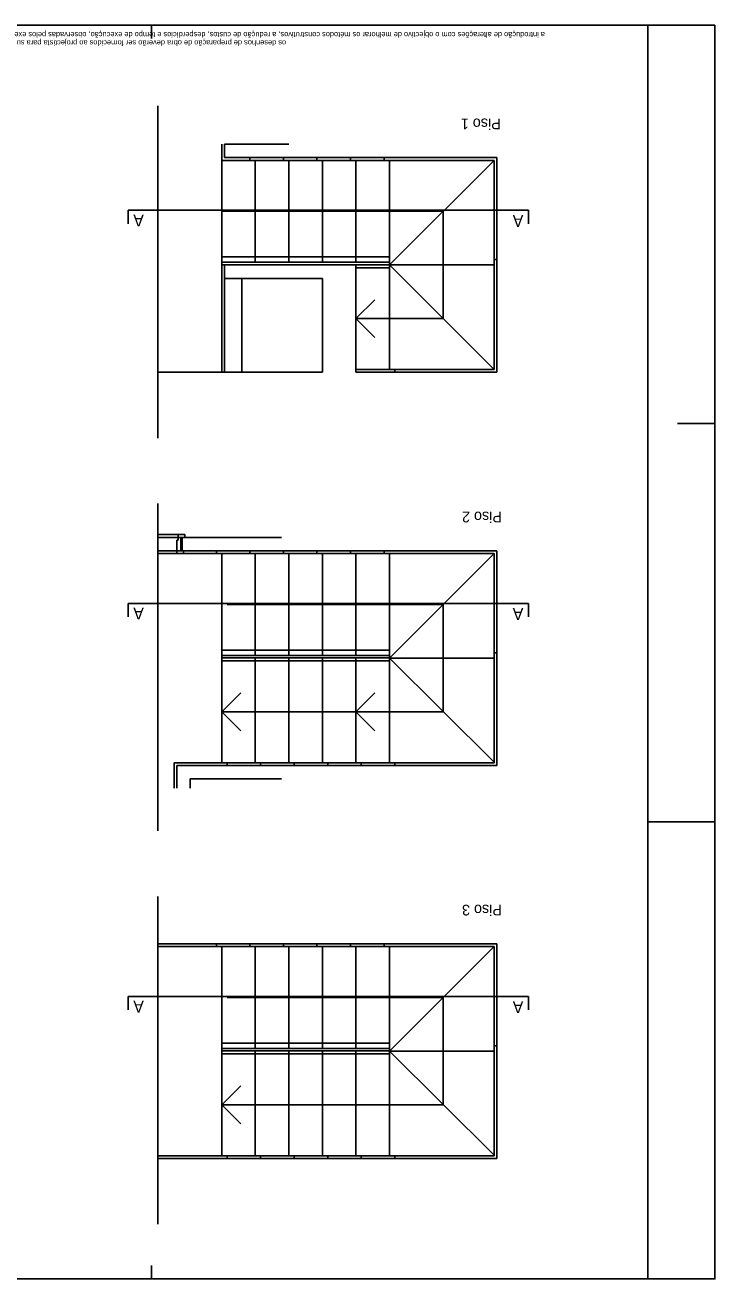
# Model space of a CAD drawing. Extents: x 1295.6 to 1307.2, y -287.2 to -277.8.
# Drawn here: x 1302.05 to 1307.19, y -287.18 to -277.84 of the extents above; entities that cross this region are included whole.
import ezdxf

# ---------------------------------------------------------------- set-up
doc = ezdxf.new("R2010")
doc.units = 0
for name, color, linetype in [('Level 1', 7, 'Continuous'), ('Level 10', 7, 'Continuous'), ('Level 13', 7, 'Continuous'), ('Level 2', 7, 'Continuous'), ('Level 4', 7, 'Continuous'), ('Level 59', 7, 'Continuous'), ('Level 60', 7, 'Continuous'), ('Level 62', 7, 'Continuous')]:
    doc.layers.add(name, color=color, linetype=linetype)

msp = doc.modelspace()

# ---------------------------------------------------------------- linework, layer by layer
at = {"layer": 'Level 1'}
for p, q in [((1303.53746, -278.72638), (1303.53746, -278.82638)), ((1303.53746, -278.82638), (1305.56746, -278.82638)), ((1305.56746, -278.82638), (1305.56746, -280.42638)), ((1304.51746, -279.62638), (1303.53746, -279.62638)), ((1303.53746, -279.62638), (1303.53746, -279.72638)), ((1304.51746, -280.42638), (1304.51746, -279.62638)), ((1304.26746, -279.72638), (1303.53746, -279.72638)), ((1304.26746, -280.42638), (1304.26746, -279.72638)), ((1304.26746, -280.42638), (1303.04022, -280.42638)), ((1305.56746, -280.42638), (1304.51746, -280.42638)), ((1303.96246, -281.65644), (1303.22279, -281.65644)), ((1303.22279, -281.65644), (1303.22279, -281.66644)), ((1303.22279, -281.65644), (1303.22279, -281.75644)), ((1303.22279, -281.74644), (1303.22279, -281.75644)), ((1303.22279, -281.75644), (1305.56746, -281.75644)), ((1305.56746, -281.75644), (1305.56746, -283.35644)), ((1305.56746, -283.35644), (1303.18279, -283.35644)), ((1303.18279, -283.35644), (1303.18279, -283.52489)), ((1303.96246, -283.45644), (1303.28279, -283.45644)), ((1303.28279, -283.45644), (1303.28279, -283.52489)), ((1303.04022, -284.6865), (1305.56746, -284.6865)), ((1305.56746, -284.6865), (1305.56746, -286.2865)), ((1305.56746, -286.2865), (1303.04022, -286.2865))]:
    msp.add_line(p, q, dxfattribs=at)
msp.add_lwpolyline([(1304.01746, -278.72638), (1303.53746, -278.72638)], dxfattribs=at)
at = {"layer": 'Level 10'}
for p, q in [((1303.19279, -281.65644), (1303.04022, -281.65644)), ((1303.18279, -281.75644), (1303.04022, -281.75644))]:
    msp.add_line(p, q, dxfattribs=at)
at = {"layer": 'Level 13'}
for p, q in [((1303.51746, -278.84638), (1303.51746, -278.72638)), ((1303.51746, -278.84638), (1305.54746, -278.84638)), ((1303.72746, -278.84638), (1303.72746, -278.82638)), ((1303.97746, -278.84638), (1303.97746, -278.82638)), ((1304.22746, -278.84638), (1304.22746, -278.82638)), ((1304.47746, -278.84638), (1304.47746, -278.82638)), ((1304.72746, -278.84638), (1304.72746, -278.82638)), ((1305.54746, -278.84638), (1305.54746, -280.40638)), ((1303.51746, -280.42638), (1303.51746, -279.62638)), ((1303.53746, -279.62638), (1303.51746, -279.62638)), ((1303.53746, -279.62638), (1303.53746, -280.42638)), ((1305.56746, -279.58638), (1305.54746, -279.58638)), ((1305.54746, -280.40638), (1304.51746, -280.40638)), ((1304.80746, -280.42638), (1304.80746, -280.40638)), ((1303.18279, -281.75644), (1303.18279, -281.67644)), ((1303.18279, -281.67644), (1303.19279, -281.67644)), ((1303.24279, -281.63644), (1303.19279, -281.63644)), ((1303.19279, -281.63644), (1303.19279, -281.65644)), ((1303.19279, -281.67644), (1303.19279, -281.65644)), ((1303.19279, -281.65644), (1303.21279, -281.65644)), ((1303.19279, -281.65644), (1303.24279, -281.65644)), ((1303.21279, -281.65644), (1303.21279, -281.75644)), ((1303.24279, -281.65644), (1303.24279, -281.63644)), ((1303.21279, -281.75644), (1303.18279, -281.75644)), ((1303.18279, -281.77644), (1303.18279, -281.75644)), ((1303.18279, -281.75644), (1303.23279, -281.75644)), ((1303.23279, -281.77644), (1303.18279, -281.77644)), ((1303.23279, -281.75644), (1303.23279, -281.77644)), ((1303.23279, -281.77644), (1305.54746, -281.77644)), ((1303.47746, -281.77644), (1303.47746, -281.75644)), ((1303.72746, -281.77644), (1303.72746, -281.75644)), ((1303.97746, -281.77644), (1303.97746, -281.75644)), ((1304.22746, -281.77644), (1304.22746, -281.75644)), ((1304.47746, -281.77644), (1304.47746, -281.75644)), ((1304.72746, -281.77644), (1304.72746, -281.75644)), ((1305.54746, -281.77644), (1305.54746, -283.33644)), ((1305.56746, -282.51644), (1305.54746, -282.51644)), ((1303.16279, -283.33644), (1305.54746, -283.33644)), ((1303.16279, -283.33644), (1303.16279, -283.52489)), ((1303.55746, -283.35644), (1303.55746, -283.33644)), ((1303.80746, -283.35644), (1303.80746, -283.33644)), ((1304.05746, -283.35644), (1304.05746, -283.33644)), ((1304.30746, -283.35644), (1304.30746, -283.33644)), ((1304.55746, -283.35644), (1304.55746, -283.33644)), ((1304.80746, -283.35644), (1304.80746, -283.33644)), ((1303.04022, -284.7065), (1305.54746, -284.7065)), ((1303.47746, -284.7065), (1303.47746, -284.6865)), ((1303.72746, -284.7065), (1303.72746, -284.6865)), ((1303.97746, -284.7065), (1303.97746, -284.6865)), ((1304.22746, -284.7065), (1304.22746, -284.6865)), ((1304.47746, -284.7065), (1304.47746, -284.6865)), ((1304.72746, -284.7065), (1304.72746, -284.6865)), ((1305.54746, -284.7065), (1305.54746, -286.2665)), ((1305.56746, -285.4465), (1305.54746, -285.4465)), ((1303.04022, -286.2665), (1305.54746, -286.2665)), ((1303.55746, -286.2865), (1303.55746, -286.2665)), ((1303.80746, -286.2865), (1303.80746, -286.2665)), ((1304.05746, -286.2865), (1304.05746, -286.2665)), ((1304.30746, -286.2865), (1304.30746, -286.2665)), ((1304.55746, -286.2865), (1304.55746, -286.2665)), ((1304.80746, -286.2865), (1304.80746, -286.2665))]:
    msp.add_line(p, q, dxfattribs=at)
at = {"layer": 'Level 2'}
for p, q in [((1303.51746, -279.62638), (1303.51746, -278.84638)), ((1303.76746, -279.56638), (1303.76746, -278.84638)), ((1304.01746, -279.56638), (1304.01746, -278.84638)), ((1304.26746, -279.56638), (1304.26746, -278.84638)), ((1304.51746, -279.56638), (1304.51746, -278.84638)), ((1304.76746, -279.59638), (1304.76746, -278.84638)), ((1304.76746, -279.62638), (1305.54746, -278.84638)), ((1303.51746, -279.22638), (1305.16746, -279.22638)), ((1305.16746, -280.02638), (1305.16746, -279.22638)), ((1304.76746, -279.56638), (1303.51746, -279.56638)), ((1304.76746, -279.60638), (1303.51746, -279.60638)), ((1304.76746, -279.59638), (1304.76746, -279.65638)), ((1305.54746, -279.62638), (1304.76746, -279.62638)), ((1304.76746, -279.62638), (1305.54746, -280.40638)), ((1304.76746, -279.64638), (1304.51746, -279.64638)), ((1304.76746, -280.40638), (1304.76746, -279.65638)), ((1303.66746, -280.42638), (1303.66746, -279.72638)), ((1304.65888, -279.88496), (1304.51746, -280.02638)), ((1304.65888, -280.1678), (1304.51746, -280.02638)), ((1305.16746, -280.02638), (1304.51746, -280.02638)), ((1303.51746, -281.77644), (1303.51746, -281.77644)), ((1303.51746, -282.58644), (1303.51746, -281.77644)), ((1303.76746, -282.49644), (1303.76746, -281.77644)), ((1304.01746, -282.49644), (1304.01746, -281.77644)), ((1304.26746, -282.49644), (1304.26746, -281.77644)), ((1304.51746, -282.49644), (1304.51746, -281.77644)), ((1304.76746, -282.52644), (1304.76746, -281.77644)), ((1304.76746, -282.55644), (1305.54746, -281.77644)), ((1303.55746, -282.15644), (1305.16746, -282.15644)), ((1305.16746, -282.95644), (1305.16746, -282.15644)), ((1304.76746, -282.49644), (1303.51746, -282.49644)), ((1304.76746, -282.52644), (1304.76746, -282.58644)), ((1304.76746, -282.53644), (1303.51746, -282.53644)), ((1304.76746, -282.57644), (1303.51746, -282.57644)), ((1303.51746, -283.33644), (1303.51746, -282.58644)), ((1303.76746, -283.33644), (1303.76746, -282.57644)), ((1304.01746, -283.33644), (1304.01746, -282.57644)), ((1304.26746, -283.33644), (1304.26746, -282.57644)), ((1304.51746, -283.33644), (1304.51746, -282.57644)), ((1305.54746, -282.55644), (1304.76746, -282.55644)), ((1304.76746, -282.55644), (1305.55246, -283.33644)), ((1304.76746, -283.33644), (1304.76746, -282.58644)), ((1303.65888, -282.81502), (1303.51746, -282.95644)), ((1304.65888, -282.81502), (1304.51746, -282.95644)), ((1305.16746, -282.95644), (1303.51746, -282.95644)), ((1303.65888, -283.09786), (1303.51746, -282.95644)), ((1304.65888, -283.09786), (1304.51746, -282.95644)), ((1303.51746, -284.7065), (1303.51746, -284.7065)), ((1303.51746, -285.5165), (1303.51746, -284.7065)), ((1303.76746, -285.4265), (1303.76746, -284.7065)), ((1304.01746, -285.4265), (1304.01746, -284.7065)), ((1304.26746, -285.4265), (1304.26746, -284.7065)), ((1304.51746, -285.4265), (1304.51746, -284.7065)), ((1304.76746, -285.4565), (1304.76746, -284.7065)), ((1304.76746, -285.4865), (1305.54746, -284.7065)), ((1303.55746, -285.0865), (1305.16746, -285.0865)), ((1305.16746, -285.8865), (1305.16746, -285.0865)), ((1304.76746, -285.4265), (1303.51746, -285.4265)), ((1304.76746, -285.4665), (1303.51746, -285.4665)), ((1304.76746, -285.5065), (1303.51746, -285.5065)), ((1303.51746, -286.2665), (1303.51746, -285.5165)), ((1303.76746, -286.2665), (1303.76746, -285.5065)), ((1304.01746, -286.2665), (1304.01746, -285.5065)), ((1304.26746, -286.2665), (1304.26746, -285.5065)), ((1304.51746, -286.2665), (1304.51746, -285.5065)), ((1304.76746, -285.4565), (1304.76746, -285.5165)), ((1305.54746, -285.4865), (1304.76746, -285.4865)), ((1304.76746, -285.4865), (1305.55246, -286.2665)), ((1304.76746, -286.2665), (1304.76746, -285.5165)), ((1303.65888, -285.74508), (1303.51746, -285.8865)), ((1305.16746, -285.8865), (1303.51746, -285.8865)), ((1303.65888, -286.02792), (1303.51746, -285.8865))]:
    msp.add_line(p, q, dxfattribs=at)
at = {"layer": 'Level 4'}
for p, q in [((1303.76746, -279.56638), (1303.76746, -279.60638)), ((1304.01746, -279.56638), (1304.01746, -279.60638)), ((1304.26746, -279.56638), (1304.26746, -279.60638)), ((1304.51746, -279.56638), (1304.51746, -279.60638)), ((1304.76746, -279.62438), (1304.51746, -279.62438)), ((1303.19279, -281.63644), (1303.04022, -281.63644)), ((1303.04022, -281.77644), (1303.18279, -281.77644)), ((1303.76746, -282.49644), (1303.76746, -282.53644)), ((1304.01746, -282.49644), (1304.01746, -282.53644)), ((1304.26746, -282.49644), (1304.26746, -282.53644)), ((1304.51746, -282.49644), (1304.51746, -282.53644)), ((1304.76746, -282.55444), (1303.51746, -282.55444)), ((1303.76746, -282.57644), (1303.76746, -282.55444)), ((1304.01746, -282.57644), (1304.01746, -282.55444)), ((1304.26746, -282.57644), (1304.26746, -282.55444)), ((1304.51746, -282.57644), (1304.51746, -282.55444)), ((1303.76746, -285.4265), (1303.76746, -285.4665)), ((1304.01746, -285.4265), (1304.01746, -285.4665)), ((1304.26746, -285.4265), (1304.26746, -285.4665)), ((1304.51746, -285.4265), (1304.51746, -285.4665)), ((1304.76746, -285.4845), (1303.51746, -285.4845)), ((1303.76746, -285.5065), (1303.76746, -285.4845)), ((1304.01746, -285.5065), (1304.01746, -285.4845)), ((1304.26746, -285.5065), (1304.26746, -285.4845)), ((1304.51746, -285.5065), (1304.51746, -285.4845))]:
    msp.add_line(p, q, dxfattribs=at)
at = {"layer": 'Level 59'}
for p, q in [((1303.04022, -280.91634), (1303.04022, -278.43903)), ((1305.80335, -279.21861), (1302.8203, -279.21861)), ((1302.8203, -279.21861), (1302.8203, -279.31841)), ((1305.80335, -279.21861), (1305.80335, -279.31841)), ((1303.04022, -283.84509), (1303.04022, -281.40311)), ((1305.80335, -282.14867), (1302.8203, -282.14867)), ((1302.8203, -282.14867), (1302.8203, -282.24847)), ((1305.80335, -282.14867), (1305.80335, -282.24847)), ((1303.04022, -286.77515), (1303.04022, -284.33317)), ((1305.80335, -285.07873), (1302.8203, -285.07873)), ((1302.8203, -285.07873), (1302.8203, -285.17853)), ((1305.80335, -285.07873), (1305.80335, -285.17853))]:
    msp.add_line(p, q, dxfattribs=at)
at = {"layer": 'Level 62'}
for p, q in [((1302.99396, -277.93814), (1302.99396, -277.83814)), ((1306.69356, -287.18414), (1306.69356, -277.83814)), ((1307.19356, -280.80814), (1306.91356, -280.80814)), ((1306.69356, -283.77814), (1307.19356, -283.77814)), ((1302.99316, -287.08414), (1302.99316, -287.18414)), ((1306.69356, -287.18414), (1307.19356, -287.18414))]:
    msp.add_line(p, q, dxfattribs=at)
msp.add_lwpolyline([(1307.19356, -277.83814), (1307.19356, -287.18414), (1295.59396, -287.18414), (1295.59396, -277.83814)], close=True, dxfattribs=at)

# ---------------------------------------------------------------- texts
at = {"layer": 'Level 59'}
for rotation, p in [(180.000181, (1302.93687, -279.25043)), (179.999819, (1305.76533, -279.25427)), (180.000181, (1302.93687, -282.18049)), (179.999819, (1305.76533, -282.18433)), (180.000181, (1302.93687, -285.11055)), (179.999819, (1305.76533, -285.11439))]:
    msp.add_text('A', height=0.088, rotation=rotation, dxfattribs=at).set_placement(p)
at = {"layer": 'Level 60'}
for s, height, rotation, p in [('os desenhos de preparação de obra deverão ser fornecidos ao projectista para sua aprovação -', 0.0399996, 180, (1303.99717, -277.95114)), ('a introdução de alterações com o objectivo de melhorar os métodos construtivos, a redução de custos, desperdícios e tempo de execução, observadas pelos exe', 0.0399996, 180, (1305.92617, -277.89014)), ('Piso 1', 0.08, 180.000011, (1305.59695, -278.53492)), ('Piso 2', 0.08, 180.000011, (1305.60601, -281.46498)), ('Piso 3', 0.08, 180.000011, (1305.60601, -284.39504))]:
    msp.add_text(s, height=height, rotation=rotation, dxfattribs=at).set_placement(p)

doc.saveas('drawing.dxf')
